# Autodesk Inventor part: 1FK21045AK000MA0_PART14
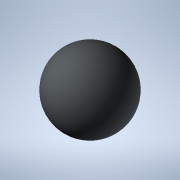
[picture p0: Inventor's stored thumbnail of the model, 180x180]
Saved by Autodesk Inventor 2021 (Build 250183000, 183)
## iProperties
Created: 2025-04
Part Number: 1FK21045AK000MA0_PART14
Material: Generic
Catalog Web Link: www.3dfindit.com
Description: -Servo synchronous motor
Document SubType Name: Modeling
Designer: psAdmin
Mass: 0.137258 g
Surface Area: 1.2868 cm^2
Volume: 0.137258 cm^3
Density: 1 g/cm^3
Appearance: PSOLRGB-212-217-219
Category: PARTsolutions
Title: 1FK21045AK000MA0_PART14
Author: Cadenas PARTsolutions
Comments: Servo synchronous motor
Sending System: PARTsolutions
Preprocessor: ST-DEVELOPER v19.3
PSOL_IDENT_0: {$CADENAS_DATA/23d-libs/siemens_ag/_cat_/3d/2f/1fk21045ak000ma0.prj},216 {VTYP=3D},{NB=1FK21045AK000
PSOL_IDENT_1: MA0_PART14},{LINA=1FK21045AK000MA0_PART14},{NN=1FK21045AK000MA0_PART14},{NOPRJ=TRUE},{DATE=19.08.202
PSOL_IDENT_2: 5 14:00:34},{GEOMDATE=30.07.2025 02:01:24},{VERSION=},{LINEID=10},{WBVAR=},{WBNUMERIC=}  {NB=1FK2104
PSOL_IDENT_3: 5AK000MA0_PART14},{LINA=1FK21045AK000MA0_PART14},{KT=DUMMY},{PREVIEW=../../../_pool_/a9/69/p_d211_xx
PSOL_IDENT_4: _00818j.png},{DESCSHORT=SIMOTICS S-1FK2 HD, SINAMICS S210 3AC 400V-480V, 1.7 Nm, 6000 rpm},{DESCLONG=
PSOL_IDENT_5: SIMOTICS S-1FK2 HD servo motor M0=2.4 Nm; PN = 1.07 kW at nN=6000 rpm (380-480 V); PN = 0.75 kW at n
PSOL_IDENT_6: N=3000 rpm (200-240 V); degree of protection IP64; cylindrical shaft D19x40mm; absolute encoder 22-b
PSOL_IDENT_7: it + 12-bit multiturn (encoder AM22DQC); with OCC interface; plug size M17, rotatable; SIMOTICS S-1F
PSOL_IDENT_8: K2 servomotorfor a wide range of uses in industrial environments. SIMOTICS S‑1FK2 servomotors are co
PSOL_IDENT_9: mpact synchronous motors with a high dynamic performance that set themselves apart as a result of th
PSOL_IDENT_10: eir high power density, degree of protection and overload capability. The motors are available in tw
PSOL_IDENT_11: o variants: as High Dynamic variant (highest dynamic performance as a result of the low intrinsic mo
PSOL_IDENT_12: ment of inertia for applications demanding a high dynamic performance with low moved masses) - and a
PSOL_IDENT_13: s Compact variant (precise and stable closed-loop control for medium up to large moved masses as a r
PSOL_IDENT_14: esult of a medium intrinsic moment of inertia). SIMOTICSS‑1FK2 servomotors fully exploit their stren
PSOL_IDENT_15: gths in a system with the SINAMICSS210 frequency converter and simple connection using the one cable
PSOL_IDENT_16: connection (OCC). Advantages include the short control and positioning times, fast and precise corr
PSOL_IDENT_17: ection of disturbing quantities as well as stable control with a high dynamic performance. The servo
PSOL_IDENT_18: motors can be configured to address a wide range of requirements. For example with and without hold
PSOL_IDENT_19: ing brake, IP64 or IP65 degree of protection, singleturn or multiturn absolute encoders - to name ju
PSOL_IDENT_20: st a few. Further, the servomotors are available in different shaft heights extending from 20 to 100
PSOL_IDENT_21: . A shaft sealing ring is available to achieve an IP65 degree of protection and for subsequent mount
PSOL_IDENT_22: ing at the motor or as spare part. SIMOTICS - the optimum motor for each and every motion control ap
PSOL_IDENT_23: plication.},{INTNO=804766789342},{SUPPLIERALTNO=1FK2104-5AK00-0MA0},{MANUID=1FK21045AK000MA0},{MANUN
PSOL_IDENT_24: AME=Siemens},{MANUTYPEDESC=Synchronous motor 1FK2-HD 2,39 Nm},{AAU732=SIMOTICS},{AAO057=S-1FK2},{AAU
PSOL_IDENT_25: 734=SIMOTICS S-1FK2 HD servo motor M0=2.4 Nm; PN = 1.07 kW at nN=6000 rpm (380-480 V); PN = 0.75 kW
PSOL_IDENT_26: at nN=3000 rpm (200-240 V); degree of protection IP64; cylindrical shaft D19x40mm; absolute encoder
PSOL_IDENT_27: 22-bit + 12-bit multiturn (encoder AM22DQC); with OCC interface; plug size M17, rotatable;},{AAW338=
PSOL_IDENT_28: Synchronous motor 1FK2-HD 2,39 Nm},{AAO742=SIMOTICS},{AAO663=4042948691151},{NOCUPEROU=1},{PRICEQUAN
PSOL_IDENT_29: TITY=1},{QUANTITYMIN=1},{QUANTITYINT=1},{CTN=85015100},{COO=DE},{AAO676=1FK2104-5AK00-0MA0},{AAO677=
PSOL_IDENT_30: Siemens AG},{ORDERUNIT=C62},{CONTENTUNIT=C62}
NB: 1FK21045AK000MA0_PART14
NT: Servo synchronous motor
NBSYN: $MANUID._PART14
LINA: 1FK21045AK000MA0_PART14
CATALOG: SIEMENS
PREVIEW: ../../../_pool_/a9/69/p_d211_xx_00818j.png
DESCSHORT: SIMOTICS S-1FK2 HD, SINAMICS S210 3AC 400V-480V, 1.7 Nm, 6000 rpm
DESCLONG: SIMOTICS S-1FK2 HD servo motor M0=2.4 Nm; PN = 1.07 kW at nN=6000 rpm (380-480 V); PN = 0.75 kW at nN=3000 rpm (200-240 V); degree of protection IP64; cylindric
INTNO: 804766789342
SUPPLIERALTNO: 1FK2104-5AK00-0MA0
MANUID: 1FK21045AK000MA0
MANUNAME: Siemens
MANUTYPEDESC: Synchronous motor 1FK2-HD 2,39 Nm
AAU732: SIMOTICS
AAO057: S-1FK2
AAU734: SIMOTICS S-1FK2 HD servo motor M0=2.4 Nm; PN = 1.07 kW at nN=6000 rpm (380-480 V); PN = 0.75 kW at nN=3000 rpm (200-240 V); degree of protection IP64; cylindric
AAW338: Synchronous motor 1FK2-HD 2,39 Nm
AAO742: SIMOTICS
AAO663: 4042948691151.0
NOCUPEROU: 1
PRICEQUANTITY: 1
QUANTITYMIN: 1
QUANTITYINT: 1
CTN: 85015100
COO: DE
ARTICLENO: 1FK21045AK000MA0_PART14
BOMINFO: 1FK21045AK000MA0_PART14
CREATOR: CADENAS GmbH
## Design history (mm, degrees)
feature "2025_04_17_15_39_51_0728"
body "Solid1"
